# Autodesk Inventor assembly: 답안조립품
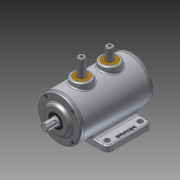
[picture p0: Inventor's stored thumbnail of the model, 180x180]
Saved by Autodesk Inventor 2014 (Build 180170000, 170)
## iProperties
Created: 2014-12
Part Number: 답안조립품
Document SubType Name: Assembly
Designer: Owner
Author: Owner
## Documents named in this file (10)
- C:\Users\Owner\Desktop\441223V1013\답안조립품.iam
- C:\Users\Owner\Desktop\441223V1013\본체.ipt
- C:\Users\Owner\Desktop\441223V1013\M4-소켓머리.ipt
- C:\Users\Owner\Desktop\441223V1013\뒷커버.ipt
- C:\Users\Owner\Desktop\441223V1013\베어링 6203.ipt
- C:\Users\Owner\Desktop\441223V1013\부시.ipt
- C:\Users\Owner\Desktop\441223V1013\슬라이더.ipt
- C:\Users\Owner\Desktop\441223V1013\앞커버.ipt
- C:\Users\Owner\Desktop\441223V1013\오일실.ipt
- C:\Users\Owner\Desktop\441223V1013\축.ipt
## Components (11 placed, 3 different names)
1. 7-베어링 6203:1
2. 8-오일실:1
3. 7-베어링 6203:2
4. 9-M4-소켓머리:1
5. 9-M4-소켓머리:3
6. 9-M4-소켓머리:4
7. 9-M4-소켓머리:5
8. 9-M4-소켓머리:2
9. 9-M4-소켓머리:6
10. 9-M4-소켓머리:7
11. 9-M4-소켓머리:8
